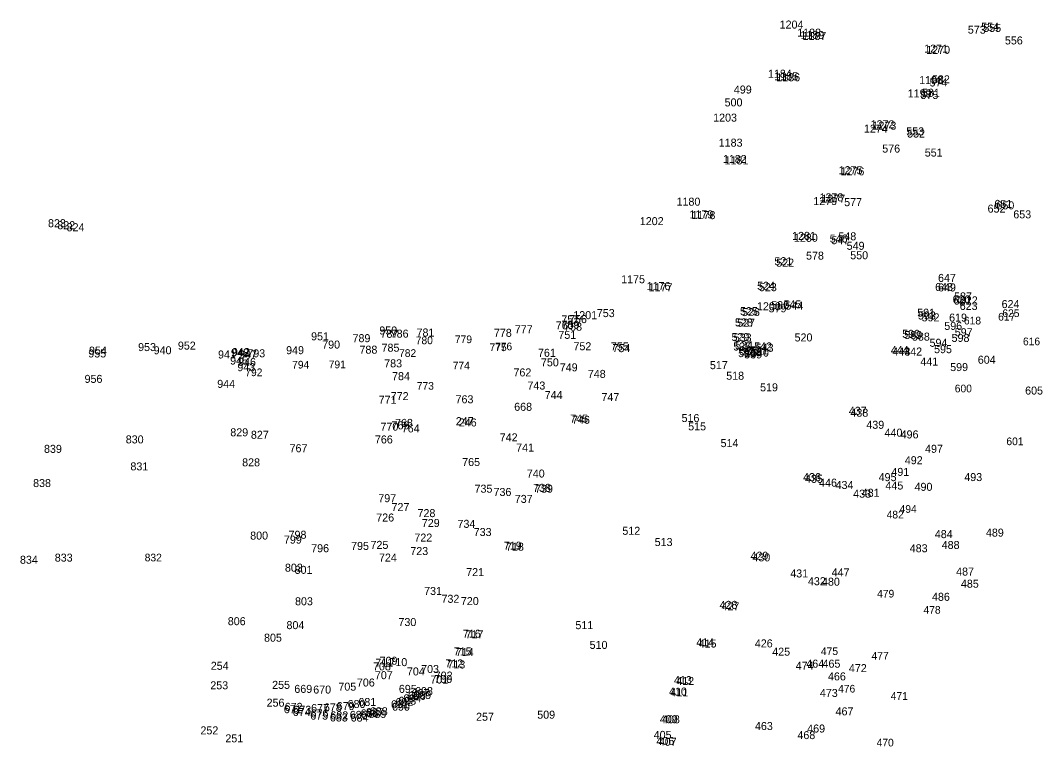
# Model space of a CAD drawing. Extents: x 359002 to 1164845, y 1141798 to 1525369.
# Drawn here: x 359876.1 to 360195.5, y 1524555 to 1524781.9 of the extents above; entities that cross this region are included whole.
import ezdxf

# ---------------------------------------------------------------- set-up
doc = ezdxf.new("R2010")
doc.units = 0
for name, color, linetype in [('BSUBM_I', 7, 'Continuous'), ('BVC_I', 7, 'Continuous'), ('CPBM_I', 7, 'Continuous'), ('DS_I', 7, 'Continuous'), ('DSM_I', 7, 'Continuous'), ('LABL_I', 7, 'Continuous'), ('LAPB_I', 7, 'Continuous'), ('LARR_I', 7, 'Continuous'), ('LELB_I', 7, 'Continuous'), ('LELS_I', 7, 'Continuous'), ('LPST_I', 7, 'Continuous'), ('LS_I', 7, 'Continuous'), ('LTD_I', 7, 'Continuous'), ('LUKL_I', 7, 'Continuous'), ('LUKP_I', 7, 'Continuous'), ('PE_I', 7, 'Continuous'), ('PELB_I', 7, 'Continuous'), ('PRC_I', 7, 'Continuous'), ('RC_I', 7, 'Continuous'), ('RCD_I', 7, 'Continuous'), ('RDP_I', 7, 'Continuous'), ('RGB_I', 7, 'Continuous'), ('RGW_I', 7, 'Continuous'), ('RSW_I', 7, 'Continuous'), ('S_I', 7, 'Continuous'), ('SDEL_I', 7, 'Continuous'), ('SRM_I', 7, 'Continuous'), ('TCBP_I', 7, 'Continuous'), ('TCPP_I', 7, 'Continuous'), ('UEO_I', 7, 'Continuous'), ('UGMK_I', 7, 'Continuous'), ('UGV_I', 7, 'Continuous'), ('ULP_I', 7, 'Continuous'), ('UP_I', 7, 'Continuous'), ('UPGW_I', 7, 'Continuous'), ('UPL_I', 7, 'Continuous'), ('USMH_I', 7, 'Continuous'), ('UUMH_I', 7, 'Continuous'), ('UUPB_I', 7, 'Continuous'), ('UWFH_I', 7, 'Continuous'), ('UWV_I', 7, 'Continuous')]:
    doc.layers.add(name, color=color, linetype=linetype)

msp = doc.modelspace()

# ---------------------------------------------------------------- texts
at = {"layer": 'BSUBM_I'}
for s, p in [('1204', (360113.32, 1524779.37)), ('1203', (360092.55, 1524750.29)), ('653', (360186.33, 1524720.07)), ('1202', (360069.63, 1524717.94)), ('620', (360167.37, 1524693.52)), ('620', (360167.37, 1524693.52)), ('622', (360169.64, 1524693.19)), ('621', (360167.68, 1524693.11)), ('757', (360045.12, 1524687.25)), ('756', (360047.51, 1524687.33)), ('756', (360047.51, 1524687.33))]:
    msp.add_text(s, height=2.501, dxfattribs=at).set_placement(p)
at = {"layer": 'BVC_I'}
for s, p in [('1198', (360156.92, 1524762.01)), ('582', (360160.92, 1524762.25)), ('499', (360099.02, 1524759.07)), ('1199', (360153.34, 1524757.85)), ('581', (360157.79, 1524758.05)), ('500', (360096.13, 1524755.05)), ('587', (360167.83, 1524694.44)), ('1200', (360106.24, 1524691.35)), ('580', (360110.7, 1524691.69)), ('1201', (360048.85, 1524688.57))]:
    msp.add_text(s, height=2.501, dxfattribs=at).set_placement(p)
at = {"layer": 'CPBM_I'}
msp.add_text('246', height=2.501, dxfattribs=at).set_placement((360013.08, 1524655.05))
at = {"layer": 'DS_I'}
for s, p in [('1274', (360139.65, 1524746.84)), ('1279', (360123.85, 1524724.22)), ('652', (360178.29, 1524721.86)), ('548', (360131.68, 1524713.21)), ('647', (360162.81, 1524700.2)), ('405', (360073.97, 1524557.43))]:
    msp.add_text(s, height=2.501, dxfattribs=at).set_placement(p)
at = {"layer": 'DSM_I'}
msp.add_text('549', height=2.501, dxfattribs=at).set_placement((360134.27, 1524710.24))
at = {"layer": 'LABL_I'}
for s, p in [('784', (359992.22, 1524669.51)), ('944', (359937.59, 1524667.1)), ('768', (359993.15, 1524654.91)), ('767', (359960.2, 1524646.99)), ('828', (359945.38, 1524642.58)), ('838', (359880.06, 1524636.11)), ('727', (359992.05, 1524628.62)), ('728', (360000.18, 1524626.72)), ('726', (359987.28, 1524625.35)), ('729', (360001.52, 1524623.64)), ('725', (359985.49, 1524616.79)), ('723', (359997.92, 1524614.87)), ('724', (359988.13, 1524612.83))]:
    msp.add_text(s, height=2.501, dxfattribs=at).set_placement(p)
at = {"layer": 'LAPB_I'}
for s, p in [('484', (360161.81, 1524620.16)), ('483', (360153.97, 1524615.74)), ('802', (359958.75, 1524609.67)), ('485', (360169.96, 1524604.66)), ('486', (360160.93, 1524600.57)), ('803', (359961.9, 1524599.18)), ('806', (359940.89, 1524592.95)), ('804', (359959.23, 1524591.72)), ('805', (359952.22, 1524587.8)), ('464', (360121.67, 1524579.68)), ('465', (360126.72, 1524579.68)), ('466', (360128.42, 1524575.7)), ('467', (360130.8, 1524564.78)), ('463', (360105.61, 1524560.2)), ('468', (360118.88, 1524557.36))]:
    msp.add_text(s, height=2.501, dxfattribs=at).set_placement(p)
at = {"layer": 'LARR_I'}
for s, p in [('788', (359982.04, 1524677.79)), ('788', (359982.04, 1524677.79)), ('785', (359988.94, 1524678.4)), ('783', (359989.76, 1524673.51)), ('771', (359988.03, 1524662.12)), ('772', (359991.8, 1524663.27)), ('770', (359988.6, 1524653.73)), ('769', (359992.06, 1524654.13)), ('769', (359992.06, 1524654.13))]:
    msp.add_text(s, height=2.501, dxfattribs=at).set_placement(p)
at = {"layer": 'LELB_I'}
for s, p in [('622', (360169.64, 1524693.19)), ('623', (360169.59, 1524691.45)), ('624', (360182.67, 1524692.03)), ('757', (360045.12, 1524687.25)), ('777', (360030.57, 1524684.18)), ('760', (360043.36, 1524685.39)), ('760', (360043.36, 1524685.39)), ('759', (360045.18, 1524685.57)), ('596', (360164.77, 1524685.21)), ('789', (359979.87, 1524681.38)), ('787', (359988.6, 1524682.76)), ('786', (359991.79, 1524682.8)), ('781', (359999.87, 1524683.15)), ('778', (360024.04, 1524683.05)), ('597', (360168.03, 1524683.23)), ('790', (359970.39, 1524679.38)), ('595', (360161.58, 1524677.95)), ('955', (359897.31, 1524676.61)), ('942', (359942.17, 1524677.06)), ('793', (359946.99, 1524676.66)), ('761', (360037.81, 1524676.8)), ('604', (360175.24, 1524674.64)), ('943', (359943.88, 1524672.31)), ('956', (359896.14, 1524668.66)), ('762', (360030.15, 1524670.68)), ('605', (360190.03, 1524665.01)), ('763', (360012.06, 1524662.29)), ('764', (359995.25, 1524653.18)), ('830', (359909.01, 1524649.75)), ('827', (359948.12, 1524651.2)), ('766', (359986.86, 1524649.74)), ('496', (360151.13, 1524651.31)), ('839', (359883.47, 1524646.8)), ('767', (359960.2, 1524646.99)), ('828', (359945.38, 1524642.58)), ('831', (359910.47, 1524641.32)), ('838', (359880.06, 1524636.11)), ('495', (360144.25, 1524637.96)), ('481', (360138.98, 1524633.07)), ('833', (359886.83, 1524612.82)), ('480', (360126.56, 1524605.29)), ('474', (360118.34, 1524579.05)), ('704', (359996.86, 1524577.26)), ('695', (359994.35, 1524571.8)), ('695', (359994.35, 1524571.8)), ('696', (359997.16, 1524569.63)), ('473', (360125.89, 1524570.53)), ('681', (359981.7, 1524567.71)), ('692', (359993.29, 1524567.68)), ('469', (360121.94, 1524559.42))]:
    msp.add_text(s, height=2.501, dxfattribs=at).set_placement(p)
at = {"layer": 'LELS_I'}
for s, p in [('618', (360170.9, 1524686.92)), ('617', (360181.6, 1524688.12)), ('625', (360182.91, 1524689.24)), ('780', (359999.62, 1524680.75)), ('779', (360011.85, 1524681.08)), ('775', (360022.69, 1524678.59)), ('776', (360024.4, 1524678.85)), ('616', (360189.35, 1524680.42)), ('782', (359994.4, 1524676.78)), ('794', (359961, 1524673.15)), ('791', (359972.42, 1524673.23)), ('774', (360011.17, 1524672.88)), ('792', (359946.35, 1524670.76)), ('773', (359999.94, 1524666.53)), ('600', (360168.04, 1524665.71)), ('601', (360184.17, 1524649.2)), ('482', (360146.75, 1524626.3)), ('494', (360150.8, 1524628.06)), ('832', (359914.93, 1524612.89)), ('479', (360143.78, 1524601.6)), ('478', (360158.27, 1524596.54)), ('475', (360126.22, 1524583.63)), ('477', (360142.05, 1524582.21)), ('476', (360131.59, 1524571.91)), ('471', (360148.02, 1524569.63)), ('470', (360143.62, 1524555.07))]:
    msp.add_text(s, height=2.4, dxfattribs=at).set_placement(p)
at = {"layer": 'LPST_I'}
for s, p in [('598', (360167.05, 1524681.47)), ('599', (360166.61, 1524672.35)), ('488', (360163.96, 1524616.77)), ('487', (360168.47, 1524608.46))]:
    msp.add_text(s, height=2.501, dxfattribs=at).set_placement(p)
at = {"layer": 'LS_I'}
for s, p in [('945', (359941.62, 1524674.38)), ('948', (359941.93, 1524676.85)), ('947', (359944.38, 1524676.33)), ('946', (359944.1, 1524673.94))]:
    msp.add_text(s, height=2.501, dxfattribs=at).set_placement(p)
at = {"layer": 'LTD_I'}
msp.add_text('765', height=2.501, dxfattribs=at).set_placement((360014.13, 1524642.68))
at = {"layer": 'LUKL_I'}
for s, p in [('598', (360167.05, 1524681.47)), ('599', (360166.61, 1524672.35)), ('488', (360163.96, 1524616.77)), ('487', (360168.47, 1524608.46))]:
    msp.add_text(s, height=2.501, dxfattribs=at).set_placement(p)
at = {"layer": 'LUKP_I'}
for s, p in [('573', (360172.12, 1524777.78)), ('574', (360160.18, 1524761.28)), ('575', (360157.33, 1524757.37)), ('576', (360145.39, 1524740.62)), ('577', (360133.48, 1524723.88)), ('823', (359884.72, 1524717.3)), ('822', (359887.62, 1524716.67)), ('824', (359890.53, 1524716.04)), ('578', (360121.57, 1524707.17)), ('579', (360109.88, 1524690.71)), ('829', (359941.68, 1524651.97)), ('799', (359958.43, 1524618.44))]:
    msp.add_text(s, height=2.501, dxfattribs=at).set_placement(p)
at = {"layer": 'PE_I'}
for s, p in [('555', (360176.94, 1524778.31)), ('1187', (360120.46, 1524775.82)), ('1271', (360158.48, 1524771.84)), ('1186', (360112.27, 1524762.91)), ('1272', (360141.74, 1524748.21)), ('552', (360153.17, 1524745.32)), ('1181', (360096.13, 1524736.93)), ('1275', (360131.76, 1524733.87)), ('1278', (360125.78, 1524725.38)), ('651', (360180.43, 1524723.34)), ('1178', (360085.8, 1524719.82)), ('1281', (360117.21, 1524713.34)), ('547', (360129.5, 1524712)), ('521', (360111.68, 1524705.44)), ('1177', (360072.39, 1524697.29)), ('524', (360106.28, 1524697.75)), ('648', (360161.91, 1524697.36)), ('544', (360115.12, 1524691.55)), ('525', (360100.94, 1524689.82)), ('591', (360156.31, 1524689.34)), ('528', (360099.37, 1524686.3)), ('529', (360098.28, 1524681.72)), ('590', (360151.61, 1524682.74)), ('754', (360061.1, 1524678.26)), ('535', (360098.83, 1524678.78)), ('543', (360105.85, 1524678.38)), ('444', (360148.07, 1524677.68)), ('536', (360100.36, 1524676.71)), ('539', (360102.25, 1524676.31)), ('540', (360104.39, 1524676.87)), ('437', (360134.94, 1524658.69)), ('746', (360048.46, 1524655.88)), ('436', (360120.65, 1524637.97)), ('739', (360036.9, 1524634.35)), ('718', (360027.83, 1524616.24)), ('429', (360104.22, 1524613.41)), ('428', (360094.55, 1524598.05)), ('717', (360015.18, 1524588.85)), ('414', (360087.27, 1524586.34)), ('714', (360012.15, 1524583.28)), ('713', (360009.51, 1524579.43)), ('253', (359935.43, 1524572.92)), ('700', (360005.44, 1524574.9)), ('413', (360080.29, 1524574.54)), ('699', (359998.86, 1524569.88)), ('410', (360078.75, 1524570.97)), ('256', (359953.02, 1524567.49)), ('671', (359958.4, 1524565.45)), ('690', (359992.22, 1524566.25)), ('674', (359961.18, 1524564.58)), ('675', (359966.65, 1524563.45)), ('683', (359972.79, 1524562.87)), ('684', (359979.28, 1524562.85)), ('689', (359984.85, 1524563.95)), ('409', (360075.89, 1524562.33)), ('406', (360074.82, 1524555.51))]:
    msp.add_text(s, height=2.501, dxfattribs=at).set_placement(p)
at = {"layer": 'PELB_I'}
for s, p in [('556', (360183.71, 1524774.41)), ('551', (360158.67, 1524739.38)), ('550', (360135.38, 1524707.29)), ('520', (360117.99, 1524681.61)), ('536', (360100.36, 1524676.71)), ('518', (360096.63, 1524669.64)), ('519', (360107.21, 1524666.03)), ('515', (360084.74, 1524653.83)), ('514', (360094.86, 1524648.6)), ('512', (360064.18, 1524621.2)), ('513', (360074.28, 1524617.68)), ('510', (360053.95, 1524585.55)), ('509', (360037.58, 1524563.74))]:
    msp.add_text(s, height=2.501, dxfattribs=at).set_placement(p)
at = {"layer": 'PRC_I'}
for s, p in [('525', (360100.94, 1524689.82)), ('517', (360091.53, 1524672.95)), ('516', (360082.67, 1524656.43)), ('512', (360064.18, 1524621.2)), ('511', (360049.51, 1524591.72)), ('509', (360037.58, 1524563.74)), ('252', (359932.35, 1524558.84)), ('251', (359940.14, 1524556.35))]:
    msp.add_text(s, height=2.501, dxfattribs=at).set_placement(p)
at = {"layer": 'RC_I'}
for s, p in [('554', (360176.3, 1524778.69)), ('1189', (360119.81, 1524776.09)), ('1270', (360159.13, 1524771.47)), ('1185', (360111.64, 1524763.21)), ('1273', (360142.33, 1524747.78)), ('553', (360152.89, 1524745.99)), ('1182', (360095.59, 1524737.37)), ('1276', (360132.35, 1524733.5)), ('1277', (360126.37, 1524724.96)), ('650', (360181.06, 1524722.88)), ('1179', (360085.13, 1524720.06)), ('1280', (360117.8, 1524712.75)), ('546', (360128.97, 1524712.51)), ('522', (360112.27, 1524704.96)), ('1176', (360071.77, 1524697.66)), ('523', (360106.86, 1524697.31)), ('649', (360162.81, 1524697.23)), ('545', (360114.53, 1524691.95)), ('526', (360101.54, 1524689.54)), ('593', (360156.53, 1524688.47)), ('527', (360100.04, 1524686.19)), ('533', (360098.98, 1524681.58)), ('589', (360152.26, 1524682.37)), ('755', (360060.59, 1524678.8)), ('534', (360099.4, 1524679.16)), ('537', (360100.75, 1524677.3)), ('541', (360104.11, 1524677.54)), ('542', (360105.36, 1524678.79)), ('538', (360102.1, 1524677.01)), ('443', (360148.58, 1524677.21)), ('438', (360135.43, 1524658.09)), ('745', (360047.87, 1524656.25)), ('435', (360121.25, 1524637.44)), ('738', (360036.27, 1524634.61)), ('719', (360027.13, 1524616.56)), ('430', (360104.81, 1524612.89)), ('427', (360095.16, 1524597.61)), ('716', (360014.33, 1524589.05)), ('415', (360088.03, 1524585.98)), ('715', (360011.5, 1524583.51)), ('712', (360008.87, 1524579.74)), ('702', (360005.54, 1524575.96)), ('412', (360081.02, 1524574.26)), ('694', (359995.72, 1524568.86)), ('696', (359997.16, 1524569.63)), ('411', (360079.21, 1524570.7)), ('671', (359958.4, 1524565.45)), ('672', (359958.67, 1524566.19)), ('692', (359993.29, 1524567.68)), ('693', (359994.19, 1524568.11)), ('673', (359961.38, 1524565.27)), ('676', (359966.79, 1524564.13)), ('682', (359972.94, 1524563.54)), ('685', (359979, 1524563.68)), ('686', (359982.39, 1524564.17)), ('408', (360076.56, 1524562.3)), ('407', (360075.57, 1524555.28))]:
    msp.add_text(s, height=2.501, dxfattribs=at).set_placement(p)
at = {"layer": 'RCD_I'}
for s, p in [('702', (360005.54, 1524575.96)), ('701', (360004.19, 1524574.72)), ('696', (359997.16, 1524569.63)), ('697', (359998.35, 1524570.47)), ('698', (359999.42, 1524571.13)), ('691', (359991.88, 1524567)), ('692', (359993.29, 1524567.68)), ('686', (359982.39, 1524564.17)), ('687', (359984.04, 1524564.51)), ('688', (359985.29, 1524564.81))]:
    msp.add_text(s, height=2.501, dxfattribs=at).set_placement(p)
at = {"layer": 'RDP_I'}
msp.add_text('834', height=2.501, dxfattribs=at).set_placement((359875.96, 1524612.15))
at = {"layer": 'RGB_I'}
for s, p in [('950', (359988.24, 1524683.79)), ('951', (359966.92, 1524681.96)), ('951', (359966.92, 1524681.96)), ('953', (359912.87, 1524678.6)), ('952', (359925.3, 1524679.06)), ('949', (359959.12, 1524677.63))]:
    msp.add_text(s, height=2.501, dxfattribs=at).set_placement(p)
at = {"layer": 'RGW_I'}
for s, p in [('954', (359897.53, 1524677.5)), ('953', (359912.87, 1524678.6)), ('952', (359925.3, 1524679.06))]:
    msp.add_text(s, height=2.501, dxfattribs=at).set_placement(p)
at = {"layer": 'RSW_I'}
for s, p in [('1188', (360118.82, 1524776.83)), ('1189', (360119.81, 1524776.09)), ('1184', (360109.67, 1524764)), ('1183', (360094.29, 1524742.47)), ('1180', (360081.11, 1524724.03)), ('1175', (360063.81, 1524699.79)), ('523', (360106.86, 1524697.31)), ('620', (360167.37, 1524693.52)), ('545', (360114.53, 1524691.95)), ('753', (360056.2, 1524689.22)), ('593', (360156.53, 1524688.47)), ('592', (360157.7, 1524687.88)), ('759', (360045.18, 1524685.57)), ('758', (360046, 1524684.96)), ('751', (360044.19, 1524682.42)), ('588', (360154.67, 1524681.87)), ('752', (360048.9, 1524678.86)), ('594', (360160.16, 1524679.94)), ('442', (360152.26, 1524677.21)), ('441', (360157.27, 1524674.06)), ('750', (360038.74, 1524673.84)), ('749', (360044.62, 1524672.27)), ('743', (360034.52, 1524666.58)), ('744', (360039.9, 1524663.61)), ('439', (360140.41, 1524654.32)), ('440', (360146.1, 1524651.86)), ('742', (360025.86, 1524650.39)), ('741', (360031, 1524647.22)), ('735', (360017.99, 1524634.35)), ('736', (360023.93, 1524633.33)), ('434', (360130.8, 1524635.51)), ('433', (360136.3, 1524632.79)), ('734', (360012.66, 1524623.37)), ('733', (360017.73, 1524620.81)), ('431', (360116.64, 1524607.87)), ('432', (360122.16, 1524605.44)), ('731', (360002.24, 1524602.4)), ('732', (360007.66, 1524599.95)), ('426', (360105.57, 1524586.01)), ('425', (360111.01, 1524583.43)), ('254', (359935.57, 1524579.02)), ('708', (359986.27, 1524578.83)), ('709', (359988.33, 1524580.6)), ('710', (359991.39, 1524580.17)), ('707', (359986.85, 1524576.08)), ('707', (359986.85, 1524576.08)), ('704', (359996.86, 1524577.26)), ('702', (360005.54, 1524575.96)), ('255', (359954.75, 1524573.06)), ('705', (359975.45, 1524572.5)), ('706', (359981.23, 1524573.79)), ('669', (359961.68, 1524571.8)), ('670', (359967.59, 1524571.59)), ('677', (359966.93, 1524565.82)), ('678', (359970.91, 1524566.02)), ('679', (359974.93, 1524566.45)), ('680', (359978.33, 1524567.09)), ('681', (359981.7, 1524567.71)), ('676', (359966.79, 1524564.13)), ('686', (359982.39, 1524564.17))]:
    msp.add_text(s, height=2.501, dxfattribs=at).set_placement(p)
at = {"layer": 'S_I'}
for s, p in [('941', (359937.84, 1524676.29)), ('748', (360053.39, 1524670.22)), ('740', (360034.33, 1524639.09)), ('446', (360125.65, 1524636.24)), ('447', (360129.56, 1524608.2)), ('720', (360013.72, 1524599.24)), ('730', (359994.21, 1524592.68))]:
    msp.add_text(s, height=2.501, dxfattribs=at).set_placement(p)
at = {"layer": 'SDEL_I'}
msp.add_text('940', height=2.501, dxfattribs=at).set_placement((359917.73, 1524677.61))
at = {"layer": 'SRM_I'}
msp.add_text('619', height=2.501, dxfattribs=at).set_placement((360166.27, 1524687.81))
at = {"layer": 'TCBP_I'}
for s, p in [('737', (360030.56, 1524631.16)), ('703', (360001.3, 1524578.01))]:
    msp.add_text(s, height=2.501, dxfattribs=at).set_placement(p)
at = {"layer": 'TCPP_I'}
msp.add_text('711', height=2.501, dxfattribs=at).set_placement((359986.98, 1524579.98))
at = {"layer": 'UEO_I'}
for s, p in [('490', (360155.48, 1524634.94)), ('489', (360177.78, 1524620.63))]:
    msp.add_text(s, height=2.501, dxfattribs=at).set_placement(p)
at = {"layer": 'UGMK_I'}
msp.add_text('445', height=2.501, dxfattribs=at).set_placement((360146.39, 1524635.34))
at = {"layer": 'UGV_I'}
msp.add_text('668', height=2.501, dxfattribs=at).set_placement((360030.38, 1524659.94))
at = {"layer": 'ULP_I'}
msp.add_text('801', height=2.501, dxfattribs=at).set_placement((359961.77, 1524609))
at = {"layer": 'UP_I'}
msp.add_text('798', height=2.501, dxfattribs=at).set_placement((359959.89, 1524619.96))
at = {"layer": 'UPGW_I'}
for s, p in [('492', (360152.43, 1524643.25)), ('491', (360148.24, 1524639.6)), ('493', (360171.02, 1524637.98)), ('797', (359987.92, 1524631.39)), ('800', (359947.89, 1524619.7)), ('796', (359966.95, 1524615.75))]:
    msp.add_text(s, height=2.501, dxfattribs=at).set_placement(p)
at = {"layer": 'UPL_I'}
for s, p in [('490', (360155.48, 1524634.94)), ('795', (359979.42, 1524616.47))]:
    msp.add_text(s, height=2.501, dxfattribs=at).set_placement(p)
at = {"layer": 'USMH_I'}
for s, p in [('247', (360012.14, 1524655.45)), ('472', (360134.96, 1524578.29))]:
    msp.add_text(s, height=2.501, dxfattribs=at).set_placement(p)
at = {"layer": 'UUMH_I'}
msp.add_text('257', height=2.501, dxfattribs=at).set_placement((360018.47, 1524563.09))
at = {"layer": 'UUPB_I'}
msp.add_text('497', height=2.501, dxfattribs=at).set_placement((360158.76, 1524646.82))
at = {"layer": 'UWFH_I'}
msp.add_text('722', height=2.501, dxfattribs=at).set_placement((359999.19, 1524619.08))
at = {"layer": 'UWV_I'}
for s, p in [('747', (360057.65, 1524663)), ('721', (360015.39, 1524608.3))]:
    msp.add_text(s, height=2.501, dxfattribs=at).set_placement(p)

doc.saveas('drawing.dxf')
